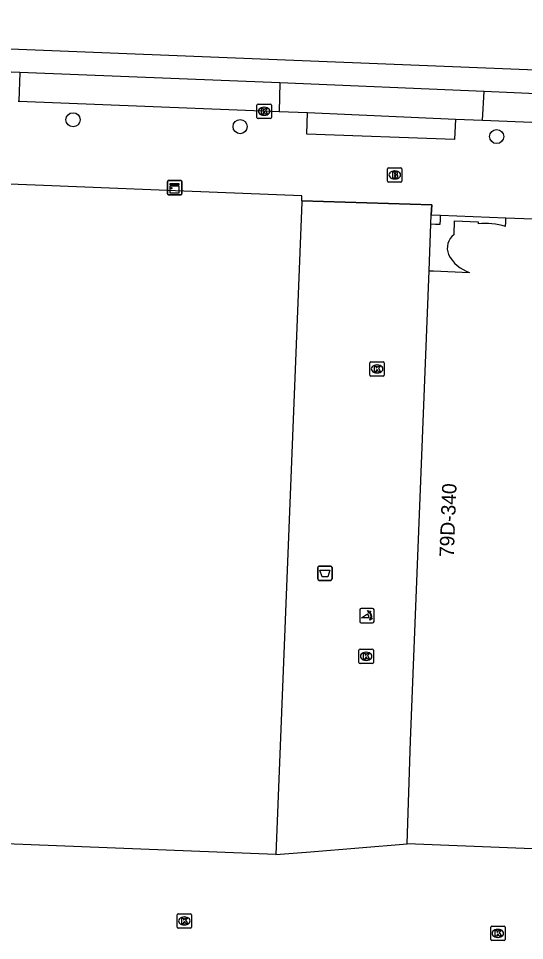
# Model space of a CAD drawing. Extents: x 160891 to 161384, y 386490 to 386907.
# Drawn here: x 161176.7 to 161211.9, y 386836.4 to 386900.6 of the extents above; entities that cross this region are included whole.
import ezdxf

# ---------------------------------------------------------------- set-up
doc = ezdxf.new("R2010")
doc.units = 0
for name, color, linetype in [('IMGEO_Afvalbak', 7, 'Continuous'), ('IMGEO_Boom', 7, 'Continuous'), ('IMGEO_Brandkraan', 7, 'Continuous'), ('IMGEO_Hek', 7, 'Continuous'), ('IMGEO_Kast', 7, 'Continuous'), ('IMGEO_Kolk', 7, 'Continuous'), ('IMGEO_Lage_trafo', 7, 'Continuous'), ('IMGEO_Pand', 7, 'Continuous'), ('IMGEO_Pand_nummerreeks', 7, 'Continuous'), ('IMGEO_Poller', 7, 'Continuous'), ('IMGEO_Rijbaan_lokaal_gesloten', 7, 'Continuous'), ('IMGEO_Voetgangersgebied_open', 7, 'Continuous'), ('IMGEO_Voetpad_open', 7, 'Continuous')]:
    doc.layers.add(name, color=color, linetype=linetype)

msp = doc.modelspace()

# ---------------------------------------------------------------- linework, layer by layer
at = {"layer": 'IMGEO_Afvalbak'}
for p, q in [((161197.497, 386861.586), (161197.497, 386862.386)), ((161197.497, 386862.386), (161197.497, 386861.586)), ((161197.597, 386862.486), (161198.387, 386862.486)), ((161198.387, 386862.486), (161197.597, 386862.486)), ((161198.487, 386862.386), (161198.487, 386861.586)), ((161198.487, 386861.586), (161198.487, 386862.386)), ((161198.387, 386861.486), (161197.597, 386861.486)), ((161197.597, 386861.486), (161198.387, 386861.486))]:
    msp.add_line(p, q, dxfattribs=at)
msp.add_lwpolyline([(161197.64, 386862.2), (161198.344, 386862.2), (161198.195, 386861.73), (161197.789, 386861.73), (161197.64, 386862.2)], dxfattribs=at)
for centre, start, end in [((161197.597, 386862.386), 90, 180), ((161197.597, 386862.386), 90, 180), ((161198.387, 386862.386), 0, 90), ((161198.387, 386862.386), 360, 90), ((161197.597, 386861.586), 180, 270), ((161197.597, 386861.586), 180, 270), ((161198.387, 386861.586), 270, 0), ((161198.387, 386861.586), 270, 0)]:
    msp.add_arc(centre, 0.1, start, end, dxfattribs=at)
at = {"layer": 'IMGEO_Boom'}
for centre in [(161180.477, 386893.518), (161192.094, 386893.037), (161209.931, 386892.348)]:
    msp.add_circle(centre, 0.489, dxfattribs=at)
at = {"layer": 'IMGEO_Brandkraan'}
for p, q in [((161202.346, 386889.252), (161202.346, 386890.104)), ((161202.421, 386890.178), (161203.273, 386890.178)), ((161203.347, 386890.104), (161203.347, 386889.252)), ((161202.834, 386889.958), (161202.859, 386889.958)), ((161203.273, 386889.178), (161202.421, 386889.178)), ((161202.857, 386889.398), (161202.832, 386889.398))]:
    msp.add_line(p, q, dxfattribs=at)
for points in [[(161202.346, 386889.252), (161202.346, 386890.104)], [(161202.421, 386890.178), (161203.273, 386890.178)], [(161203.347, 386890.104), (161203.347, 386889.252)], [(161202.694, 386889.878), (161202.694, 386889.478), (161202.907, 386889.478)], [(161202.925, 386889.878), (161202.694, 386889.878)], [(161202.873, 386889.797), (161202.819, 386889.797), (161202.819, 386889.721)], [(161202.819, 386889.721), (161202.872, 386889.721)], [(161202.881, 386889.645), (161202.819, 386889.645), (161202.819, 386889.564)], [(161202.819, 386889.564), (161202.881, 386889.564)], [(161203.273, 386889.178), (161202.421, 386889.178)]]:
    msp.add_lwpolyline(points, dxfattribs=at)
for centre, radius, start, end in [((161202.423, 386890.102), 0.0765, 91.55205, 178.44795), ((161202.423, 386890.102), 0.0765, 91.55205, 178.44795), ((161203.271, 386890.102), 0.0765, 1.55205, 88.44795), ((161203.271, 386890.102), 0.0765, 1.55205, 88.44795), ((161202.874, 386889.759), 0.0379, 267.82845, 90.93552), ((161202.882, 386889.604), 0.0404, 269.87594, 90.50774), ((161202.913, 386889.729), 0.251, 268.66757, 293.53466), ((161202.929, 386889.733), 0.145, 59.4692, 91.53667), ((161202.954, 386889.78), 0.0922, 285.51372, 58.15012), ((161202.959, 386889.588), 0.105, 301.31148, 78.98903), ((161202.423, 386889.254), 0.0765, 181.55205, 268.44795), ((161202.423, 386889.254), 0.0765, 181.55205, 268.44795), ((161203.271, 386889.254), 0.0765, 271.55205, 358.44795), ((161203.271, 386889.254), 0.0765, 271.55205, 358.44795)]:
    msp.add_arc(centre, radius, start, end, dxfattribs=at)
for centre, major_axis, ratio, start_param, end_param in [((161202.833, 386889.678), (-0.387, 0.002), 0.722429, 4.712389, 7.853982), ((161202.858, 386889.678), (-0.39, 0.002), 0.717154, 1.570796, 4.712389)]:
    msp.add_ellipse(centre, major_axis=major_axis, ratio=ratio, start_param=start_param, end_param=end_param, dxfattribs=at)
at = {"layer": 'IMGEO_Hek'}
msp.add_lwpolyline([(161196.381, 386887.886), (161205.414, 386887.602), (161205.385, 386886.913)], dxfattribs=at)
at = {"layer": 'IMGEO_Kast'}
for p, q in [((161187.04, 386888.371), (161187.04, 386889.212)), ((161187.04, 386889.212), (161187.04, 386888.371)), ((161187.115, 386889.296), (161187.956, 386889.296)), ((161187.956, 386889.296), (161187.115, 386889.296)), ((161188.04, 386889.221), (161188.04, 386888.38)), ((161188.04, 386888.38), (161188.04, 386889.221)), ((161187.965, 386888.296), (161187.124, 386888.296)), ((161187.124, 386888.296), (161187.965, 386888.296))]:
    msp.add_line(p, q, dxfattribs=at)
for points in [[(161187.235, 386889.086), (161187.835, 386889.086), (161187.835, 386889.001), (161187.235, 386889.001), (161187.235, 386889.086)], [(161187.235, 386888.911), (161187.835, 386888.911), (161187.835, 386888.422), (161187.235, 386888.422), (161187.235, 386888.911)]]:
    msp.add_lwpolyline(points, dxfattribs=at)
msp.add_circle((161187.319, 386888.76), 0.0377, dxfattribs=at)
for centre, start, end in [((161187.118, 386889.218), 92.4484, 184.28452), ((161187.118, 386889.218), 92.4484, 184.28452), ((161187.962, 386889.218), 2.4484, 94.28452), ((161187.962, 386889.218), 2.4484, 94.28452), ((161187.118, 386888.374), 182.4484, 274.28452), ((161187.118, 386888.374), 182.4484, 274.28452), ((161187.962, 386888.374), 272.4484, 4.28452), ((161187.962, 386888.374), 272.4484, 4.28452)]:
    msp.add_arc(centre, 0.0779, start, end, dxfattribs=at)
at = {"layer": 'IMGEO_Kolk'}
for p, q in [((161193.339, 386894.608), (161194.191, 386894.608)), ((161193.264, 386893.682), (161193.264, 386894.534)), ((161193.752, 386894.388), (161193.777, 386894.388)), ((161194.265, 386894.534), (161194.265, 386893.682)), ((161194.191, 386893.608), (161193.339, 386893.608)), ((161193.775, 386893.828), (161193.75, 386893.828)), ((161201.118, 386875.762), (161201.118, 386876.614)), ((161201.193, 386876.688), (161202.045, 386876.688)), ((161202.119, 386876.614), (161202.119, 386875.762)), ((161201.606, 386876.468), (161201.631, 386876.468)), ((161202.045, 386875.688), (161201.193, 386875.688)), ((161201.629, 386875.908), (161201.604, 386875.908)), ((161200.357, 386855.781), (161200.357, 386856.633)), ((161200.432, 386856.707), (161201.284, 386856.707)), ((161200.845, 386856.487), (161200.87, 386856.487)), ((161201.358, 386856.633), (161201.358, 386855.781)), ((161201.284, 386855.707), (161200.432, 386855.707)), ((161200.868, 386855.927), (161200.843, 386855.927)), ((161187.716, 386837.383), (161187.716, 386838.235)), ((161187.791, 386838.309), (161188.643, 386838.309)), ((161188.717, 386838.235), (161188.717, 386837.383)), ((161188.227, 386837.529), (161188.202, 386837.529)), ((161188.204, 386838.089), (161188.229, 386838.089)), ((161188.643, 386837.309), (161187.791, 386837.309)), ((161209.516, 386836.517), (161209.516, 386837.369)), ((161209.591, 386837.443), (161210.443, 386837.443)), ((161210.004, 386837.223), (161210.029, 386837.223)), ((161210.517, 386837.369), (161210.517, 386836.517)), ((161210.443, 386836.443), (161209.591, 386836.443)), ((161210.027, 386836.663), (161210.002, 386836.663))]:
    msp.add_line(p, q, dxfattribs=at)
for points in [[(161193.339, 386894.608), (161194.191, 386894.608)], [(161193.264, 386893.682), (161193.264, 386894.534)], [(161193.585, 386894.308), (161193.708, 386894.308), (161193.708, 386894.157), (161193.838, 386894.308), (161194.002, 386894.308), (161193.856, 386894.157), (161194.009, 386893.908), (161193.857, 386893.908), (161193.772, 386894.072), (161193.708, 386894.005), (161193.708, 386893.908), (161193.585, 386893.908), (161193.585, 386894.308)], [(161194.265, 386894.534), (161194.265, 386893.682)], [(161194.191, 386893.608), (161193.339, 386893.608)], [(161201.118, 386875.762), (161201.118, 386876.614)], [(161201.193, 386876.688), (161202.045, 386876.688)], [(161202.119, 386876.614), (161202.119, 386875.762)], [(161201.439, 386876.388), (161201.562, 386876.388), (161201.562, 386876.237), (161201.692, 386876.388), (161201.856, 386876.388), (161201.71, 386876.237), (161201.863, 386875.988), (161201.711, 386875.988), (161201.626, 386876.152), (161201.562, 386876.085), (161201.562, 386875.988), (161201.439, 386875.988), (161201.439, 386876.388)], [(161202.045, 386875.688), (161201.193, 386875.688)], [(161200.357, 386855.781), (161200.357, 386856.633)], [(161200.432, 386856.707), (161201.284, 386856.707)], [(161200.678, 386856.407), (161200.801, 386856.407), (161200.801, 386856.256), (161200.931, 386856.407), (161201.095, 386856.407), (161200.949, 386856.256), (161201.102, 386856.007), (161200.95, 386856.007), (161200.865, 386856.171), (161200.801, 386856.104), (161200.801, 386856.007), (161200.678, 386856.007), (161200.678, 386856.407)], [(161201.358, 386856.633), (161201.358, 386855.781)], [(161201.284, 386855.707), (161200.432, 386855.707)], [(161187.716, 386837.383), (161187.716, 386838.235)], [(161187.791, 386838.309), (161188.643, 386838.309)], [(161188.717, 386838.235), (161188.717, 386837.383)], [(161188.037, 386838.009), (161188.16, 386838.009), (161188.16, 386837.858), (161188.29, 386838.009), (161188.454, 386838.009), (161188.308, 386837.858), (161188.461, 386837.609), (161188.309, 386837.609), (161188.224, 386837.773), (161188.16, 386837.706), (161188.16, 386837.609), (161188.037, 386837.609), (161188.037, 386838.009)], [(161188.643, 386837.309), (161187.791, 386837.309)], [(161209.516, 386836.517), (161209.516, 386837.369)], [(161209.591, 386837.443), (161210.443, 386837.443)], [(161209.837, 386837.143), (161209.96, 386837.143), (161209.96, 386836.992), (161210.09, 386837.143), (161210.254, 386837.143), (161210.108, 386836.992), (161210.261, 386836.743), (161210.109, 386836.743), (161210.024, 386836.907), (161209.96, 386836.84), (161209.96, 386836.743), (161209.837, 386836.743), (161209.837, 386837.143)], [(161210.517, 386837.369), (161210.517, 386836.517)], [(161210.443, 386836.443), (161209.591, 386836.443)]]:
    msp.add_lwpolyline(points, dxfattribs=at)
for centre, start, end in [((161193.341, 386894.532), 91.55205, 178.44795), ((161193.341, 386894.532), 91.55205, 178.44795), ((161194.189, 386894.532), 1.55205, 88.44795), ((161194.189, 386894.532), 1.55205, 88.44795), ((161193.341, 386893.684), 181.55205, 268.44795), ((161193.341, 386893.684), 181.55205, 268.44795), ((161194.189, 386893.684), 271.55205, 358.44795), ((161194.189, 386893.684), 271.55205, 358.44795), ((161201.195, 386876.612), 91.55205, 178.44795), ((161201.195, 386876.612), 91.55205, 178.44795), ((161202.043, 386876.612), 1.55205, 88.44795), ((161202.043, 386876.612), 1.55205, 88.44795), ((161201.195, 386875.764), 181.55205, 268.44795), ((161201.195, 386875.764), 181.55205, 268.44795), ((161202.043, 386875.764), 271.55205, 358.44795), ((161202.043, 386875.764), 271.55205, 358.44795), ((161200.434, 386856.631), 91.55205, 178.44795), ((161200.434, 386856.631), 91.55205, 178.44795), ((161201.282, 386856.631), 1.55205, 88.44795), ((161201.282, 386856.631), 1.55205, 88.44795), ((161200.434, 386855.783), 181.55205, 268.44795), ((161200.434, 386855.783), 181.55205, 268.44795), ((161201.282, 386855.783), 271.55205, 358.44795), ((161201.282, 386855.783), 271.55205, 358.44795), ((161187.793, 386838.233), 91.55205, 178.44795), ((161187.793, 386838.233), 91.55205, 178.44795), ((161188.641, 386838.233), 1.55205, 88.44795), ((161188.641, 386838.233), 1.55205, 88.44795), ((161187.793, 386837.385), 181.55205, 268.44795), ((161187.793, 386837.385), 181.55205, 268.44795), ((161188.641, 386837.385), 271.55205, 358.44795), ((161188.641, 386837.385), 271.55205, 358.44795), ((161209.593, 386837.367), 91.55205, 178.44795), ((161209.593, 386837.367), 91.55205, 178.44795), ((161210.441, 386837.367), 1.55205, 88.44795), ((161210.441, 386837.367), 1.55205, 88.44795), ((161209.593, 386836.519), 181.55205, 268.44795), ((161209.593, 386836.519), 181.55205, 268.44795), ((161210.441, 386836.519), 271.55205, 358.44795), ((161210.441, 386836.519), 271.55205, 358.44795)]:
    msp.add_arc(centre, 0.0765, start, end, dxfattribs=at)
for centre, major_axis, ratio, start_param, end_param in [((161193.751, 386894.108), (-0.387, 0.002), 0.722429, 4.712389, 7.853982), ((161193.776, 386894.108), (-0.39, 0.002), 0.717154, 1.570796, 4.712389), ((161201.605, 386876.188), (-0.387, 0.002), 0.722429, 4.712389, 7.853982), ((161201.63, 386876.188), (-0.39, 0.002), 0.717154, 1.570796, 4.712389), ((161200.844, 386856.207), (-0.387, 0.002), 0.722429, 4.712389, 7.853982), ((161200.869, 386856.207), (-0.39, 0.002), 0.717154, 1.570796, 4.712389), ((161188.203, 386837.809), (-0.387, 0.002), 0.722429, 4.712389, 7.853982), ((161188.228, 386837.809), (-0.39, 0.002), 0.717154, 1.570796, 4.712389), ((161210.003, 386836.943), (-0.387, 0.002), 0.722429, 4.712389, 7.853982), ((161210.028, 386836.943), (-0.39, 0.002), 0.717154, 1.570796, 4.712389)]:
    msp.add_ellipse(centre, major_axis=major_axis, ratio=ratio, start_param=start_param, end_param=end_param, dxfattribs=at)
at = {"layer": 'IMGEO_Lage_trafo'}
for points in [[(161205.361, 386886.272), (161205.385, 386886.913)], [(161205.361, 386886.272), (161205.681, 386886.26), (161206.004, 386886.249), (161206.017, 386886.568), (161206.029, 386886.888)], [(161205.385, 386886.913), (161206.029, 386886.888)]]:
    msp.add_lwpolyline(points, dxfattribs=at)
at = {"layer": 'IMGEO_Pand'}
for points in [[(161196.381, 386887.886), (161196.395, 386888.23), (161188.186, 386888.554), (161178.427, 386888.94), (161127.058, 386890.969)], [(161196.381, 386887.886), (161196.377, 386887.78), (161194.586, 386842.427)], [(161206.97, 386885.531), (161207.007, 386886.478), (161208.657, 386886.418), (161208.652, 386886.278)], [(161210.538, 386886.09), (161210.559, 386886.386), (161210.581, 386886.706)], [(161210.581, 386886.706), (161222.369, 386886.248)], [(161203.707, 386843.159), (161203.943, 386850.322), (161205.23, 386883.017)], [(161205.23, 386883.017), (161205.549, 386883.004), (161208.047, 386882.906)], [(161194.586, 386842.427), (161120.067, 386845.369), (161120.551, 386857.609)], [(161282.19, 386840.045), (161203.707, 386843.159)]]:
    msp.add_lwpolyline(points, dxfattribs=at)
for centre, radius, start, end in [((161209.138, 386881.603), 4.701, 72.67666, 95.93825), ((161207.669, 386884.592), 1.171, 126.67252, 202.31343), ((161208.783, 386885.253), 2.46, 206.72065, 252.58899)]:
    msp.add_arc(centre, radius, start, end, dxfattribs=at)
at = {"layer": 'IMGEO_Poller'}
for p, q in [((161200.408, 386859.43), (161200.408, 386858.623)), ((161200.408, 386859.43), (161200.408, 386858.623)), ((161201.31, 386859.525), (161200.502, 386859.525)), ((161201.31, 386859.525), (161200.502, 386859.525)), ((161201.404, 386858.623), (161201.404, 386859.43)), ((161201.404, 386858.623), (161201.404, 386859.43)), ((161200.502, 386858.528), (161201.31, 386858.528)), ((161200.502, 386858.528), (161201.31, 386858.528))]:
    msp.add_line(p, q, dxfattribs=at)
for points in [[(161201.087, 386859.254), (161201.075, 386859.181), (161200.95, 386859.386)], [(161200.95, 386859.386), (161201.181, 386859.32), (161201.11, 386859.288)], [(161201.043, 386858.881), (161200.53, 386858.881), (161200.96, 386859.156)], [(161201.103, 386858.709), (161201.169, 386858.94), (161201.199, 386858.872)], [(161201.235, 386858.845), (161201.307, 386858.834), (161201.103, 386858.709)]]:
    msp.add_lwpolyline(points, dxfattribs=at)
for centre, radius, start, end in [((161200.502, 386859.43), 0.0946, 90, 180), ((161200.502, 386859.43), 0.0946, 90, 180), ((161201.31, 386859.43), 0.0946, 0, 90), ((161201.31, 386859.43), 0.0946, 0, 90), ((161200.715, 386858.931), 0.332, 351.32473, 42.4854), ((161200.729, 386858.941), 0.476, 351.75274, 41.16905), ((161200.729, 386858.941), 0.516, 349.35686, 42.29123), ((161200.502, 386858.623), 0.0946, 180, 270), ((161200.502, 386858.623), 0.0946, 180, 270), ((161201.31, 386858.623), 0.0946, 270, 0), ((161201.31, 386858.623), 0.0946, 270, 0)]:
    msp.add_arc(centre, radius, start, end, dxfattribs=at)
at = {"layer": 'IMGEO_Rijbaan_lokaal_gesloten'}
for points in [[(161123.263, 386900.56), (161248.069, 386895.57), (161278.544, 386894.358), (161279.11, 386894.349)], [(161176.778, 386896.8), (161155.904, 386897.594)], [(161176.778, 386896.8), (161176.703, 386894.8)], [(161194.86, 386896.072), (161176.778, 386896.8)], [(161194.86, 386896.072), (161194.801, 386894.087)], [(161209.056, 386895.484), (161194.86, 386896.072)], [(161208.945, 386893.49), (161209.056, 386895.484)], [(161221.008, 386894.938), (161209.056, 386895.484)], [(161176.66, 386894.802), (161176.703, 386894.8)], [(161194.801, 386894.087), (161196.781, 386894.009)], [(161196.781, 386894.009), (161207.063, 386893.567)], [(161207.063, 386893.567), (161208.945, 386893.49)]]:
    msp.add_lwpolyline(points, dxfattribs=at)
at = {"layer": 'IMGEO_Voetgangersgebied_open'}
for points in [[(161205.23, 386883.017), (161205.361, 386886.272)], [(161194.586, 386842.427), (161196.993, 386842.62), (161203.707, 386843.159)]]:
    msp.add_lwpolyline(points, dxfattribs=at)
at = {"layer": 'IMGEO_Voetpad_open'}
for points in [[(161176.703, 386894.8), (161194.801, 386894.087)], [(161207.063, 386893.567), (161206.996, 386892.136), (161196.74, 386892.515), (161196.781, 386894.009)], [(161208.945, 386893.49), (161220.937, 386892.996)], [(161205.385, 386886.913), (161205.414, 386887.602), (161196.381, 386887.886)], [(161206.029, 386886.888), (161210.581, 386886.706)]]:
    msp.add_lwpolyline(points, dxfattribs=at)

# ---------------------------------------------------------------- texts
at = {"layer": 'IMGEO_Pand_nummerreeks'}
msp.add_text('79D-340', height=1, rotation=87.74849, dxfattribs=at).set_placement((161206.948, 386863.088))

doc.saveas('drawing.dxf')
